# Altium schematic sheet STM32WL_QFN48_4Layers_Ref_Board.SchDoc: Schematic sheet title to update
size A3; Date: Not used; ApprovedBy: Not used; CheckedBy: Not used; Author: Not used; CompanyName: STMicroelectronics; DrawnBy: Not used; Engineer: Not used; Organization: Not used; Address1: Not used; Address2: Not used; Address3: Not used; Address4: Not used; DocumentNumber: Not used; Revision: Not used; SheetNumber: 2; SheetTotal: 2
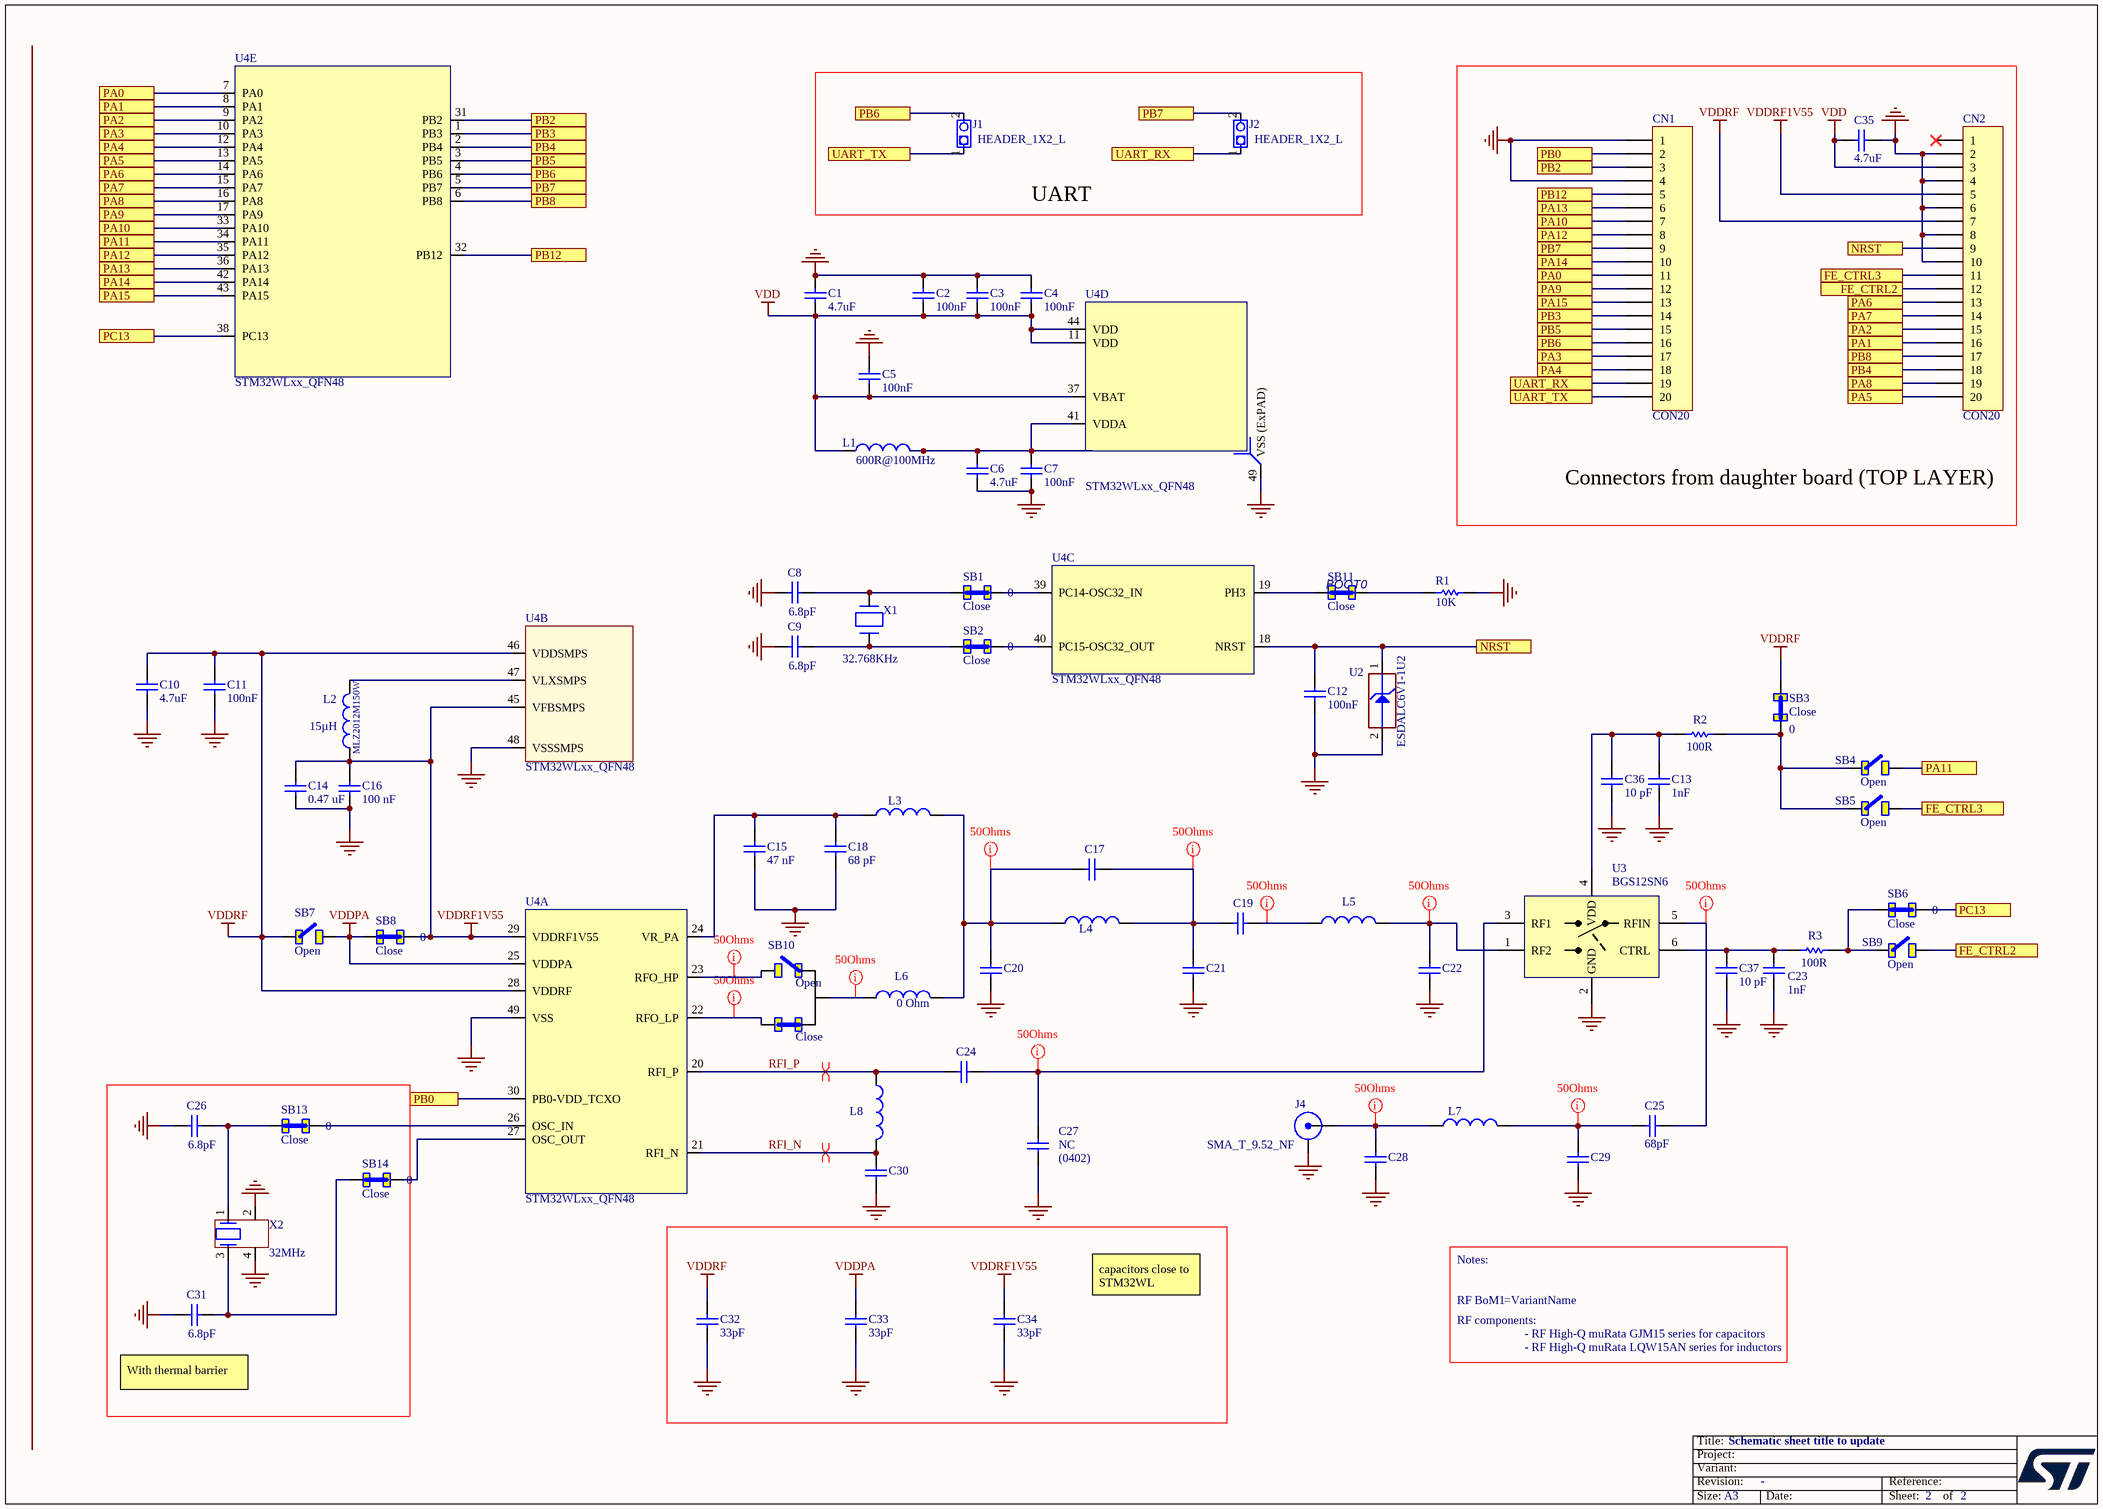
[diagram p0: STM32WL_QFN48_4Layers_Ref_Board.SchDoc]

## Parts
C1  value 4.7uF  [CAPC1608X09N]
C2  value 100nF  [CAPC1005X06N]
C3  value 100nF  [CAPC1005X06N]
C4  value 100nF  [CAPC1005X06N]
C5  value 100nF  [CAPC1005X06N]
C6  value 4.7uF  [CAPC1608X09N]
C7  value 100nF  [CAPC1005X06N]
C8  value 6.8pF  [CAPC1005X06N]  (hidden comment: Capacitor)
C9  value 6.8pF  [CAPC1005X06N]  (hidden comment: Capacitor)
C10  value 4.7uF  [CAPC1608X09N]
C11  value 100nF  [CAPC1005X06N]
C12  value 100nF  [CAPC1005X06N]
C13  value 1nF  [CAPC1005X06N]
C14  value 0.47 uF  [CAPC1608X09N]
C15  value 47 nF  [0402]
C16  value 100 nF  [CAPC1608X09N]
C17  (no value)  [CAPC1005X06N]
C18  value 68 pF  [0402]
C19  (no value)  [CAPC1005X06N]
C20  (no value)  [CAPC1005X06N]
C21  (no value)  [CAPC1005X06N]
C22  (no value)  [CAPC1005X06N]
C23  value 1nF  [CAPC1005X06N]
C24  (no value)  [CAPC1005X06N]
C25  value 68pF  [CAPC1005X06N]
C26  value 6.8pF  [CAPC1005X06N]  (hidden comment: Capacitor)
C27  NC  value (0402)  [CAPC1005X06N]
C28  (no value)  [CAPC1005X06N - duplicate - duplicate]
C29  (no value)  [CAPC1005X06N - duplicate - duplicate]
C30  (no value)  [CAPC1005X06N]
C31  value 6.8pF  [CAPC1005X06N]  (hidden comment: Capacitor)
C32  value 33pF  [CAPC1005X06N]
C33  value 33pF  [CAPC1005X06N]
C34  value 33pF  [CAPC1005X06N]
C35  value 4.7uF  [CAPC1608X09N]
C36  value 10 pF  [CAPC1005X06N]  (hidden comment: Capa_0402)
C37  value 10 pF  [CAPC1005X06N]  (hidden comment: Capa_0402)
CN1  CON20  [CO_SAMTEC_TSW-120-07-x-S]
CN2  CON20  [CO_SAMTEC_TSW-120-07-x-S]
J1  HEADER_1X2_L  [CO_MOLEX_22-03-2021]
J2  HEADER_1X2_L  [CO_MOLEX_22-03-2021]
J4  SMA_T_9.52_NF  [CO_SAMTEC_SMA-J-P-ST-EMI]
L1  value 600R@100MHz  [INDC1608X95N]
L2  value 15µH  Manufacturer_Part_Number: MLZ2012M150W  [INDC2012X13N]
L3  (no value)  [IND_MURATA_LQW15A]
L4  (no value)  [IND_MURATA_LQW15A]
L5  (no value)  [IND_MURATA_LQW15A]
L6  value 0 Ohm  [IND_MURATA_LQW15A]
L7  (no value)  [IND_MURATA_LQW15A]
L8  (no value)  [IND_MURATA_LQW15A]
R1  value 10K  [RESC1608X05N]
R2  value 100R  [RESC1005X04N]
R3  value 100R  [RESC1005X04N]
RF_BoM1  RF-BOM  (value not drawn)  (mechanical)
SB1  Close  value 0  [SB_0402]
SB2  Close  value 0  [SB_0402]
SB3  Close  value 0  [SB_0402]
SB4  Open  [SB_0402]
SB5  Open  [SB_0402]
SB6  Close  value 0  [SB_0402]
SB7  Open  [SB_0402]
SB8  Close  value 0  [SB_0402]
SB9  Open  [SB_0402]
SB10  SB_3Pads  [SB3Pads_0402]  (value not drawn)
SB11  Close  [SB_0402]
SB13  Close  value 0  [SB_0402]
SB14  Close  value 0  [SB_0402]
U2  Manufacturer_Part_Number: ESDALC6V1-1U2  [DIOM0603X03N]
U3  BGS12SN6  [SON40P70X40-6N]
U4  STM32WLxx_QFN48  [STM32WLxx_QFN48]  (parts A,B,C,D,E of 5)
X1  value 32.768KHz  [OSC_NDK_NX2012SA]  (hidden comment: XTAL_2_PINS)
X2  value 32MHz  [OSC_NDK_NX2016SA]

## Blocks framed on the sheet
Connectors from daughter board (TOP LAYER): C35 CN1 CN2
UART: J1 J2

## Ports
FE_CTRL2, FE_CTRL3, NRST, PA0, PA1, PA2, PA3, PA4, PA5, PA6, PA7, PA8, PA9, PA10, PA11, PA12, PA13, PA14, PA15, PB0, PB2, PB3, PB4, PB5, PB6, PB7, PB8, PB12, PC13, UART_RX, UART_TX

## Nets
GND: C1.1 C2.1 C3.1 C4.1 C5.1 C6.2 C7.2 C8.2 C9.2 C10.2 C11.2 C12.2 C13.1 C14.2 C15.2 C16.2 C18.1 C20.2 C21.1 C22.1 C23.1 C26.2 C27.1 C28.2 C29.2 C30.1 C31.2 C32.1 C33.1 C34.1 C35.2 C36.1 C37.1 CN1.1 CN1.4 CN2.2 CN2.4 CN2.6 CN2.8 CN2.10 J4.2(Y) R1.1 U2.2(GND) U3.2(GND) U4.48(VSSSMPS) U4.49(VSS_(ExPAD)) X2.2 X2.4
VDD: C1.2 C2.2 C3.2 C4.2 C5.2 C35.1 CN2.3 L1.1 U4.11(VDD) U4.37(VBAT) U4.44(VDD)
VDDPA: C33.2 SB7.1 SB8.2 U4.25(VDDPA)
VDDRF: C10.1 C11.1 C32.2 CN2.7 SB3.1 SB7.2 U4.28(VDDRF) U4.46(VDDSMPS)
VDDRF1V55: C14.1 C16.1 C34.2 CN2.5 L2.1 SB8.1 U4.29(VDDRF1V55) U4.45(VFBSMPS)
FE_CTRL2: CN2.12 SB9.1 ; port FE_CTRL2
FE_CTRL3: CN2.11 SB5.1 ; port FE_CTRL3
NRST: C12.1 CN2.9 U2.1(IO1) U4.18(NRST) ; port NRST
PA0: CN1.11 U4.7(PA0) ; port PA0
PA1: CN2.16 U4.8(PA1) ; port PA1
PA2: CN2.15 U4.9(PA2) ; port PA2
PA3: CN1.17 U4.10(PA3) ; port PA3
PA4: CN1.18 U4.12(PA4) ; port PA4
PA5: CN2.20 U4.13(PA5) ; port PA5
PA6: CN2.13 U4.14(PA6) ; port PA6
PA7: CN2.14 U4.15(PA7) ; port PA7
PA8: CN2.19 U4.16(PA8) ; port PA8
PA9: CN1.12 U4.17(PA9) ; port PA9
PA10: CN1.7 U4.33(PA10) ; port PA10
PA11: SB4.1 U4.34(PA11) ; port PA11
PA12: CN1.8 U4.35(PA12) ; port PA12
PA13: CN1.6 U4.36(PA13) ; port PA13
PA14: CN1.10 U4.42(PA14) ; port PA14
PA15: CN1.13 U4.43(PA15) ; port PA15
PB0: CN1.2 U4.30(PB0-VDD_TCXO) ; port PB0
PB2: CN1.3 U4.31(PB2) ; port PB2
PB3: CN1.14 U4.1(PB3) ; port PB3
PB4: CN2.18 U4.2(PB4) ; port PB4
PB5: CN1.15 U4.3(PB5) ; port PB5
PB6: CN1.16 J1.2 U4.4(PB6) ; port PB6
PB7: CN1.9 J2.2 U4.5(PB7) ; port PB7
PB8: CN2.17 U4.6(PB8) ; port PB8
PB12: CN1.5 U4.32(PB12) ; port PB12
PC13: SB6.1 U4.38(PC13) ; port PC13
RFI_N: C30.2 L8.2 U4.21(RFI_N)
RFI_P: C24.1 L8.1 U4.20(RFI_P)
UART_RX: CN1.19 J2.1 ; port UART_RX
UART_TX: CN1.20 J1.1 ; port UART_TX
NetC6_1: C6.1 C7.1 L1.2 U4.41(VDDA)
NetC8_1: C8.1 SB1.2 X1.2(X2)
NetC9_1: C9.1 SB2.2 X1.1(X1)
NetC13_2: C13.2 C36.2 R2.1 U3.4(VDD)
NetC15_1: C15.1 C18.2 L3.2 U4.24(VR_PA)
NetC17_1: C17.1 C20.1 L3.1 L4.1 L6.1
NetC17_2: C17.2 C19.2 C21.2 L4.2
NetC19_1: C19.1 L5.1
NetC22_2: C22.2 L5.2 U3.1(RF2)
NetC23_2: C23.2 C37.2 R3.1 U3.6(CTRL)
NetC24_2: C24.2 C27.2 U3.3(RF1)
NetC25_1: C25.1 U3.5(RFIN)
NetC25_2: C25.2 C29.1 L7.1
NetC26_1: C26.1 SB13.2 X2.1
NetC28_1: C28.1 J4.1(X) L7.2
NetC31_1: C31.1 SB14.2 X2.3
NetL2_2: L2.2 U4.47(VLXSMPS)
NetL6_2: L6.2 SB10.2
NetR1_2: R1.2 SB11.1
NetR2_2: R2.2 SB3.2 SB4.2 SB5.2
NetR3_2: R3.2 SB6.2 SB9.2
NetSB1_1: SB1.1 U4.39(PC14-OSC32_IN)
NetSB2_1: SB2.1 U4.40(PC15-OSC32_OUT)
NetSB10_1: SB10.1 U4.23(RFO_HP)
NetSB10_3: SB10.3 U4.22(RFO_LP)
NetSB11_2: SB11.2 U4.19(PH3)
NetSB13_1: SB13.1 U4.26(OSC_IN)
NetSB14_1: SB14.1 U4.27(OSC_OUT)

Not connected (* = marked no-connect by the designer): CN2 1*

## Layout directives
differential pair: RFI_N, RFI_P
net class 50Ohms: NetC17_1, NetC17_2, NetC19_1, NetC22_2, NetC24_2, NetC25_1, NetC25_2, NetC28_1, NetL6_2, NetSB10_1, NetSB10_3

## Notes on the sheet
- (near SB11) BOOT0
- Notes:
- capacitors close to STM32WL
- RF components:
- (near C31) With thermal barrier
- (near RF_BoM1) - RF High-Q muRata GJM15 series for capacitors
- (near RF_BoM1) - RF High-Q muRata LQW15AN series for inductors

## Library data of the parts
C1 C6 C10 C35 = MCD-00009: Capacitor, MLCC, 4.7uF, 16V, X5R, 10%, 0603, T=0.8mm; Manufacturer_Part_Number: CC0603KRX5R7BB475; Manufacturer: YAGEO
C2-C5 C7 C11 C12 = MCD-00102: Capacitor, MLCC, 100nF, 16V, X7R, 10%, 0402, T=0,5mm; Manufacturer_Part_Number: CC0402KRX7R7BB104; Manufacturer: YAGEO
C8 C9 C26 C31 = MCD-00003: Capacitor, MLCC, 6.8pF, 50V, NPO, +-0.1pF, 0402, T=0.5mm; Manufacturer_Part_Number: GRM1555C1H6R8BA01; Manufacturer: MURATA
C13 C23 = MCD-00198: Capacitor, MLCC, 1nF, 16V, X7R, 10%, 0402, T=0.5mm; Manufacturer_Part_Number: CC0402KRX7R7BB102; Manufacturer: YAGEO
C14 = MCD-00009: Capacitor, MLCC, 4.7 uF, 16V, X5R, 10%, 0603, T=0.8mm; Manufacturer_Part_Number: CC0603KRX5R7BB474; Manufacturer: YAGEO
C15 = MCD-01123: Capacitor, MLCC,47nF, 16V, X7R, 10%, 0402, T=0.5mm; Manufacturer_Part_Number: GCM155R71E473KA55; Manufacturer: MURATA
C16 = MCD-00009: Capacitor, MLCC, 100 nF, 16V, X5R, 10%, 0603, T=0.8mm; Manufacturer: YAGEO
C17 C19 C22 C24 C30 = MCD-01123: RF Capacitor
C18 = MCD-01123: Capacitor, MLCC,68pF, 50V, C0G, 1%, 0402, T=0.5mm; Manufacturer_Part_Number: GCM1555C1H680JA16; Manufacturer: MURATA
C20 = MCD-00102: RF Capacitor; Manufacturer_Part_Number: Not Connected
C21 = MCD-00015: RF Capacitor
C25 = MCD-01123: RF Capacitor; Manufacturer_Part_Number: GRM1555C1HR68WB01D; Manufacturer: Murata
C27 = MCD-01123: RF Capacitor; Manufacturer: MURATA
C28 = Capacitor: RF Capacitor
C29 = MCD-00102: RF Capacitor
C32-C34 = MCD-00277: Capacitor, MLCC, 33pF, 50V, NPO, 2%, 0402, T=0,5mm; Manufacturer_Part_Number: GRM1555C1H330GA01; Manufacturer: MURATA
C36 C37 = Capa_0402: 10pF ±1% 50V Ceramic Capacitor C0G, NP0 0402 (1005 Metric); Manufacturer_Part_Number: GJM1555C1H100FB01D; Manufacturer: MURATA
CN1 CN2 = CON20: Connector right-angle, pitch 2.54mm, 20 contacts; Manufacturer: SAMTEC; Manufacturer_Part_Number: TSW-120-07-L-S
J1 J2 = HEADER_1X2_L: Header 1x2 Through hole 2.54mm; Manufacturer: MOLEX
J4 = SMA_T_9.52_NF: SMA Jack, Edge Mount, 50 Ohms; Manufacturer: SAMTEC; Manufacturer_Part_Number: SMA-J-P-H-ST-EM1
L1 = MCD-00047: SMD Chip ferrite bead, 600R@100MHz +/-25%, 350mA, 500mohm DC, 0603, T=0.8mm; Manufacturer_Part_Number: FCM1608KF-601T03; Manufacturer: TAI-TECH
L2 = MCD-01433: MLZ2012 Multilayer Shielded Inductor 15µH, ±5%; Manufacturer: TDK
L3 = MCD-01330: RF Inductor; Manufacturer: MURATA
L4 L5 L7 L8 = MCD-01330: RF Inductor
L6 = MCD-01330: Résistance 0 ohm; Manufacturer_Part_Number: RCS04020000Z0ED; Manufacturer: Vishay / Dale
R1 = MCD-00220: Resistor,10K,0603,1%,1/10W; Manufacturer_Part_Number: RC0603FR-0710KL; Manufacturer: YAGEO
R2 R3 = MCD-00119: Resistor,100R,0402,1%,1/16W; Manufacturer_Part_Number: RC0402FR-07100RL; Manufacturer: YAGEO
SB1-SB3 SB6 SB8 SB13 SB14 = SB_0Ohm: Solder Bridge 0R [0402] (Populated with 0 Ohm); Manufacturer: Vishay / Dale; Manufacturer_Part_Number: RCS04020000Z0ED
SB4 SB5 SB7 SB9 = SB_Open: Solder Bridge Open [0402] (Unpopulated)
SB10 = SB_3Pads: Solder Bridge
SB11 = SB_0Ohm: Solder Bridge 0R [0402] (Populated with 0 Ohm); Manufacturer: Vishay / Dale; Manufacturer_Part_Number: RCS04020000Z0ED; VALUE: 0 ohm
U2 = MCD-00170: ESD protection 6V1; Manufacturer: STMICROELECTRONICS
U3 = BGS12SN6: DC switch - Ultra-Low  SPDT analog switch; Manufacturer: INFINEON
U4 = STM32WLxx_QFN48: HQDC : Verified April, 25 2019
X1 = MCD-01479: Crystal 32.768kHz, 6pF, -+20PPM, R=80K, SMD; Manufacturer_Part_Number: NX2012SA 32.768KHz EXS00A-MU00527; Manufacturer: NDK
X2 = MCD-01446: Crystal 32 MHz, 8pF, -+10 PPM, R=60Ω, SMD; Manufacturer_Part_Number: NX2016SA 32MHz EXS00A-CS06465; Manufacturer: NDK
